(* Logix 5000 project; controller VMPExerciser_1769 1769-L16ER-BB1B rev 30.11; software revision 30.00 *)

TASK MainTask (continuous, watchdog 500 ms) : MainProgram, VMP_Interface

MODULES
   Local : 1769-L16ER-BB1B (PointIO 0, rev 30.11)
      Pump00 : ETHERNET-MODULE (Ethernet 192.168.1.164, rev 1.1, Output RPI 20 ms)
      Pump01 : ETHERNET-MODULE (Ethernet 192.168.1.232, rev 1.1, Output RPI 20 ms)
      Pump02 : ETHERNET-MODULE (Ethernet 192.168.1.167, rev 1.1, Output RPI 20 ms)
      Pump03 : ETHERNET-MODULE (Ethernet 192.168.168.130, rev 1.1, Output RPI 20 ms)
      Discrete_IO : Embedded (PointIO 1, rev 30.11, Output RPI 20 ms)
END_MODULES

TYPE String_16 :   // string type
STRUCT
   LEN : DINT;
   DATA : SINT[16];
END_STRUCT
END_TYPE

TYPE String_20 :   // string type
STRUCT
   LEN : DINT;
   DATA : SINT[20];
END_STRUCT
END_TYPE

TYPE VMP_Cfg :
STRUCT
   ReadyInterlock : BOOL;   // ReadyInterlock
   EthernetRunReady : BOOL;   // EthernetRunReady
   HoldOnFault : BOOL;   // HoldOnFault
   Spare1_3 : BOOL;   // Spare Bit
   Spare1_4 : BOOL;   // Spare Bit
   Spare1_5 : BOOL;   // Spare Bit
   Spare1_6 : BOOL;   // Spare Bit
   Spare1_7 : BOOL;   // Spare Bit
   DecPlaces : SINT;   // DecimalPlaces
   SpareByte1 : SINT;   // Spare data1
   SpareByte2 : SINT;   // Spare data1
END_STRUCT
END_TYPE

TYPE VMP_Device :
STRUCT
   Enabled : BOOL;
   Dispense_Revs : INT;
   Dispense_Rpm : INT;
   Dispense_Vol : REAL;
   Prime_Revs : INT;
   Prime_Rpm : INT;
   Init_DN : BOOL;
   Path : STRING;
   PathFromGSV : SINT[82];
   CFG : VMP_Cfg;
   IN : VMP_IN;
   OUT : VMP_OUT;
   Name : String_16;
END_STRUCT
END_TYPE

TYPE VMP_IN :
STRUCT
   Ready : BOOL;   // Ready to Run
   Running : BOOL;   // Running
   Abort : BOOL;   // Abort State
   Direction : BOOL;   // Direction CCW
   ContinuousRun : BOOL;   // Continuous Run
   MotorRunning : BOOL;   // Motors Running
   AtMaxShot : BOOL;   // AtMaxShot
   CmdAck : BOOL;   // PLC Cmd Ack
   InvalidVolume : BOOL;   // InvaliVolume
   Spare1_9 : BOOL;   // Spare Bit
   Spare1_10 : BOOL;   // Spare Bit
   Spare1_11 : BOOL;   // Spare Bit
   Spare1_12 : BOOL;   // Spare Bit
   Spare1_13 : BOOL;   // Spare Bit
   Spare1_14 : BOOL;   // Spare Bit
   Spare1_15 : BOOL;   // Spare Bit
   Spare1_16 : BOOL;   // Spare Bit
   Spare1_17 : BOOL;   // Spare Bit
   Spare1_18 : BOOL;   // Spare Bit
   Spare1_19 : BOOL;   // Spare Bit
   Spare1_20 : BOOL;   // Spare Bit
   Spare1_21 : BOOL;   // Spare Bit
   Spare1_22 : BOOL;   // Spare Bit
   Spare1_23 : BOOL;   // Spare Bit
   Spare1_24 : BOOL;   // Spare Bit
   Spare1_25 : BOOL;   // Spare Bit
   Spare1_26 : BOOL;   // Spare Bit
   Spare1_27 : BOOL;   // Spare Bit
   Spare1_28 : BOOL;   // Spare Bit
   FaultDispenseMotor : BOOL;   // Disp Motor Fault
   FaultAdjustMotor : BOOL;   // Adj Motor Fault
   FaultAdjustSensor : BOOL;   // Adj Sensor Fault
   CurProgram : DINT;   // Program
   CurRevolutions : DINT;   // Revolutions
   CurVolume : REAL;   // Volume
   CurRpm : DINT;   // RPM
   VolumeDint : DINT;   // Vol as Dint
   Spare_In_DInt2 : DINT;   // Spare data2
   FineAdj : INT;   // FineAdj
   Spare_In_Int1 : INT;   // Spare_In_Int 1
END_STRUCT
END_TYPE

TYPE VMP_OUT :
STRUCT
   OkToRun : BOOL;   // Ok to Run
   Start : BOOL;   // Start
   Abort : BOOL;   // Abort Run
   Direction : BOOL;   // Direction CCW
   ContinuousRun : BOOL;   // Run Continuously
   SetMaxShotSize : BOOL;   // Set Max Volumn
   SetShotSize : BOOL;   // Set Volume
   IgnorePLC : BOOL;   // Ignore PLC Cmds
   IncFineAdj : BOOL;   // IncFineAdj
   DecFineAdj : BOOL;   // DecFineAdj
   ResetRevsCnt : BOOL;   // ResetRevsCnt
   Spare11 : BOOL;   // Spare11
   Spare12 : BOOL;   // Spare12
   Spare13 : BOOL;   // Spare13
   Spare14 : BOOL;   // Spare14
   Spare15 : BOOL;   // Spare15
   Spare16 : BOOL;   // Spare16
   Spare17 : BOOL;   // Spare17
   Spare18 : BOOL;   // Spare18
   Spare19 : BOOL;   // Spare19
   Spare20 : BOOL;   // Spare20
   Spare21 : BOOL;   // Spare21
   Spare22 : BOOL;   // Spare22
   Spare23 : BOOL;   // Spare23
   Spare24 : BOOL;   // Spare24
   Spare25 : BOOL;   // Spare25
   Spare26 : BOOL;   // Spare26
   Spare27 : BOOL;   // Spare27
   Spare28 : BOOL;   // Spare28
   Spare29 : BOOL;   // Spare29
   Spare30 : BOOL;   // Spare30
   Program : DINT;   // Program
   Revolutions : DINT;   // Revolutions
   Volume : REAL;   // Volume
   Rpm : DINT;   // RPM
   Spare_Out_DInt1 : DINT;   // SpareDInt1
   Spare_Out_DInt2 : DINT;   // SpareDInt2
   FineAdjOut : INT;   // FineAdj
   Spare_Out_Int1 : INT;   // Sapre_Out_Int1
END_STRUCT
END_TYPE

TYPE VMP_Prg :
STRUCT
   CalDispenseTime : BOOL;   // CalDispenseTime
   Direction : BOOL;   // Direction CCW
   SetShotSize : BOOL;   // Set Volume
   ContinuousRun : BOOL;   // Run Continuously
   Spare1_4 : BOOL;   // Spare Bit
   Spare1_5 : BOOL;   // Spare Bit
   Spare1_6 : BOOL;   // Spare Bit
   Spare1_7 : BOOL;   // Spare Bit
   Spare1_8 : BOOL;   // Spare Bit
   Spare1_9 : BOOL;   // Spare Bit
   Spare1_10 : BOOL;   // Spare Bit
   Spare1_11 : BOOL;   // Spare Bit
   Spare1_12 : BOOL;   // Spare Bit
   Spare1_13 : BOOL;   // Spare Bit
   Spare1_14 : BOOL;   // Spare Bit
   Spare1_15 : BOOL;   // Spare Bit
   Spare1_16 : BOOL;   // Spare Bit
   Spare1_17 : BOOL;   // Spare Bit
   Spare1_18 : BOOL;   // Spare Bit
   Spare1_19 : BOOL;   // Spare Bit
   Spare1_20 : BOOL;   // Spare Bit
   Spare1_21 : BOOL;   // Spare Bit
   Spare1_22 : BOOL;   // Spare Bit
   Spare1_23 : BOOL;   // Spare Bit
   Spare1_24 : BOOL;   // Spare Bit
   Spare1_25 : BOOL;   // Spare Bit
   Spare1_26 : BOOL;   // Spare Bit
   Spare1_27 : BOOL;   // Spare Bit
   Spare1_28 : BOOL;   // Spare Bit
   Spare1_29 : BOOL;   // Spare Bit
   Spare1_30 : BOOL;   // Spare Bit
   Spare1_31 : BOOL;   // Spare Bit
   Program : DINT;   // Program
   PullBack : DINT;   // PullBack
   InitialRPM : DINT;   // InitialRPM
   RPM : DINT;   // RPM
   FinalRPM : DINT;   // FinalRPM
   FineAdjust : DINT;   // FineAdjust
   Acceleration : DINT;   // Acceleration
   Deceleration : DINT;   // Deceleration
   LoopCycles : DINT;   // LoopCycles
   LinkedProgram : DINT;   // LinkedProgram
   LinkedTimeDelay : DINT;   // LinkedTimeDelay
   MotorCurrent : DINT;   // MotorCurrent
   Revolutions : DINT;   // Revolutions
   AprxDispenseTime : DINT;   // DispenseTime
   Volume : REAL;   // Volume
   ProgramName : String_16;   // ProgramName
END_STRUCT
END_TYPE

ADD_ON_INSTRUCTION ModuleToMSG_Path   (* revision 1.0, vendor Zaxis, Inc *)
VAR_IN_OUT
   Instance_Name : MODULE; {required}
   MsgTag : MESSAGE; {required}
   Pump : VMP_Device; {required}
END_VAR
VAR
   GsvPath : SINT[32]; {access None}
END_VAR

ROUTINE Logic   (* ladder *)
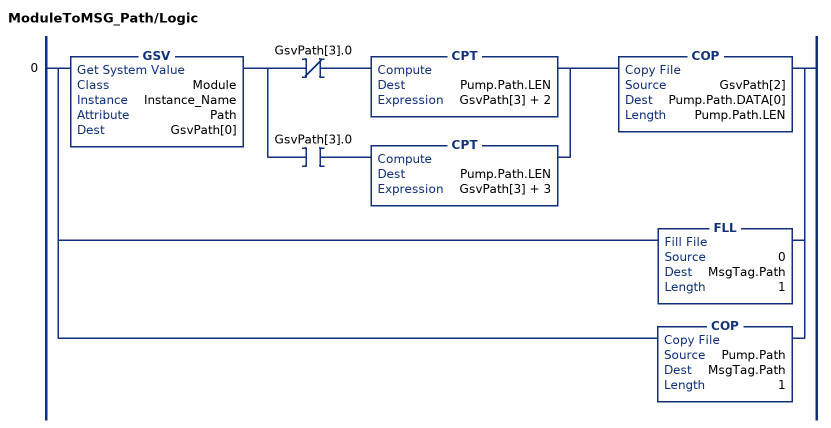
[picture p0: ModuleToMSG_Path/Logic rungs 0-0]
   0: [GSV(Module,Instance_Name,Path,GsvPath[0]) [XIO(GsvPath[3].0) CPT(Pump.Path.LEN,GsvPath[3] + 2) ,XIC(GsvPath[3].0) CPT(Pump.Path.LEN,GsvPath[3] + 3) ] COP(GsvPath[2],Pump.Path.DATA[0],Pump.Path.LEN) ,FLL(0,MsgTag.Path,1) ,COP(Pump.Path,MsgTag.Path,1) ];
END_ROUTINE
END_ADD_ON_INSTRUCTION

ADD_ON_INSTRUCTION VMP_Dispense   (* revision 1.0, vendor Zaxis, Inc *)
VAR_IN_OUT
   Pmp : VMP_Device; {required}
END_VAR
VAR
   DispenseVolDint : DINT; {access None}
END_VAR

ROUTINE Logic   (* ladder *)
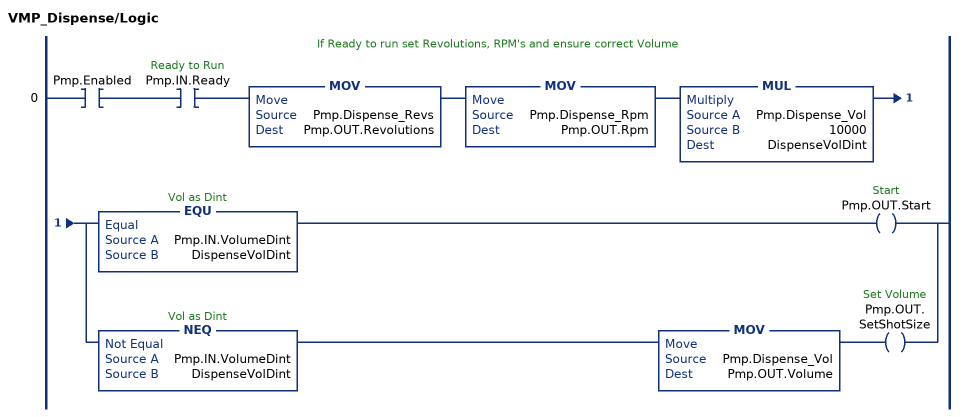
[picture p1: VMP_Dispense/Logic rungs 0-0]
   // If Ready to run set Revolutions, RPM's and ensure correct Volume
   0: XIC(Pmp.Enabled)XIC(Pmp.IN.Ready)MOV(Pmp.Dispense_Revs,Pmp.OUT.Revolutions)MOV(Pmp.Dispense_Rpm,Pmp.OUT.Rpm)MUL(Pmp.Dispense_Vol,10000,DispenseVolDint)[EQU(Pmp.IN.VolumeDint,DispenseVolDint) OTE(Pmp.OUT.Start) ,NEQ(Pmp.IN.VolumeDint,DispenseVolDint) MOV(Pmp.Dispense_Vol,Pmp.OUT.Volume) OTE(Pmp.OUT.SetShotSize) ];
END_ROUTINE
END_ADD_ON_INSTRUCTION

ADD_ON_INSTRUCTION VMP_Initialize   (* revision 1.0 *)
VAR_IN_OUT
   VMP_Module : MODULE; {required}
   Vmp : VMP_Device; {required}
   MsgTag : MESSAGE; {required}
END_VAR
VAR_OUTPUT
   MsgFlags : INT; {access Read Only, visible}
        .2   // EW
        .5   // DN
        .4   // ER
        .6   // ST
        .7   // EN
        .9   // EN_CC
        .8   // TO
END_VAR
VAR
   GsvPath : SINT[32]; {access None}
   PathSet : BOOL; {access None}
END_VAR

ROUTINE Logic   (* ladder *)
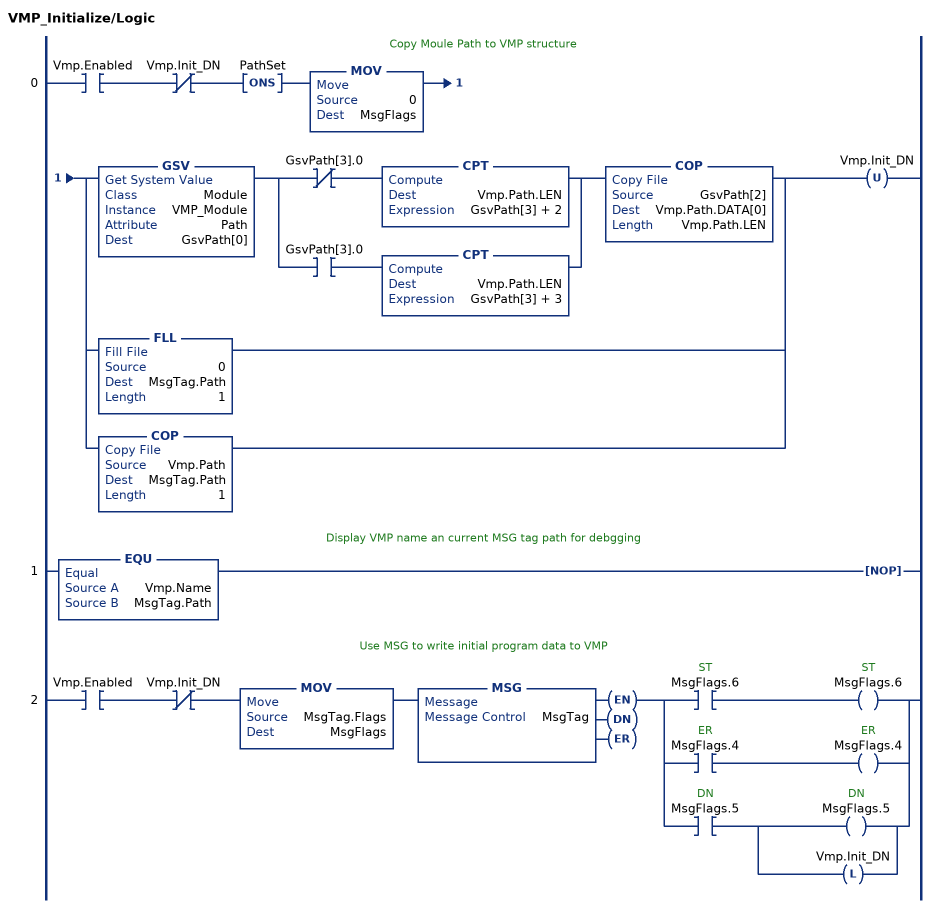
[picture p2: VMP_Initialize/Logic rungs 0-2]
   // Copy Moule Path to VMP structure
   0: XIC(Vmp.Enabled)XIO(Vmp.Init_DN)ONS(PathSet)MOV(0,MsgFlags)[GSV(Module,VMP_Module,Path,GsvPath[0]) [XIO(GsvPath[3].0) CPT(Vmp.Path.LEN,GsvPath[3] + 2) ,XIC(GsvPath[3].0) CPT(Vmp.Path.LEN,GsvPath[3] + 3) ] COP(GsvPath[2],Vmp.Path.DATA[0],Vmp.Path.LEN) ,FLL(0,MsgTag.Path,1) ,COP(Vmp.Path,MsgTag.Path,1) ]OTU(Vmp.Init_DN);
   // Display VMP name an current MSG tag path for debgging
   1: EQU(Vmp.Name,MsgTag.Path)NOP();
   // Use MSG to write initial program data to VMP
   2: XIC(Vmp.Enabled)XIO(Vmp.Init_DN)MOV(MsgTag.Flags,MsgFlags)MSG(MsgTag)[XIC(MsgFlags.6) OTE(MsgFlags.6) ,XIC(MsgFlags.4) OTE(MsgFlags.4) ,XIC(MsgFlags.5) [OTE(MsgFlags.5) ,OTL(Vmp.Init_DN) ] ];
END_ROUTINE
END_ADD_ON_INSTRUCTION

ADD_ON_INSTRUCTION VMP_Initialize1   (* revision 1.0 *)
VAR_IN_OUT
   VMP_Module : MODULE; {required}
   MsgTag : MESSAGE; {required}
   Vmp : VMP_Device; {required}
END_VAR
VAR_OUTPUT
   DN : BOOL; {access Read Only, visible}
   ER : BOOL; {access Read Only, visible}
END_VAR
VAR
   GsvPath : SINT[32]; {access None}
   MSGFlgs : INT; {access None}   // FLAGS
        .2   // EW
        .4   // ER
        .5   // DN
        .6   // ST
        .7   // EN
        .8   // TO
        .9   // EN_CC
END_VAR

ROUTINE Logic   (* ladder *)
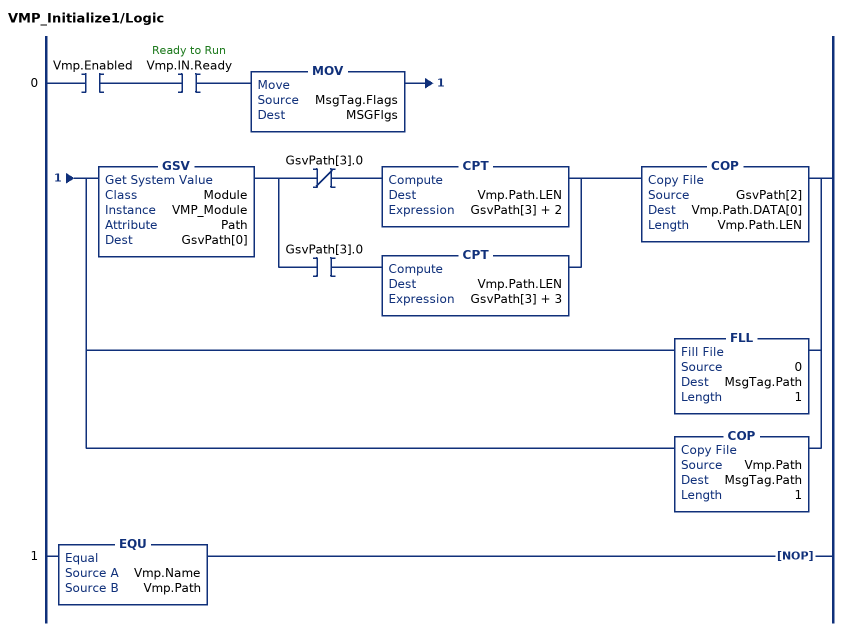
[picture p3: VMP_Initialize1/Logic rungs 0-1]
   0: XIC(Vmp.Enabled)XIC(Vmp.IN.Ready)MOV(MsgTag.Flags,MSGFlgs)[GSV(Module,VMP_Module,Path,GsvPath[0]) [XIO(GsvPath[3].0) CPT(Vmp.Path.LEN,GsvPath[3] + 2) ,XIC(GsvPath[3].0) CPT(Vmp.Path.LEN,GsvPath[3] + 3) ] COP(GsvPath[2],Vmp.Path.DATA[0],Vmp.Path.LEN) ,FLL(0,MsgTag.Path,1) ,COP(Vmp.Path,MsgTag.Path,1) ];
   1: EQU(Vmp.Name,Vmp.Path)NOP();
END_ROUTINE
END_ADD_ON_INSTRUCTION

ADD_ON_INSTRUCTION VMP_Prime   (* revision 1.0, vendor Zaxis, Inc *)
VAR_IN_OUT
   Pmp : VMP_Device; {required}
END_VAR
VAR
   PrimeStarted : BOOL; {access None}
END_VAR

ROUTINE Logic   (* ladder *)
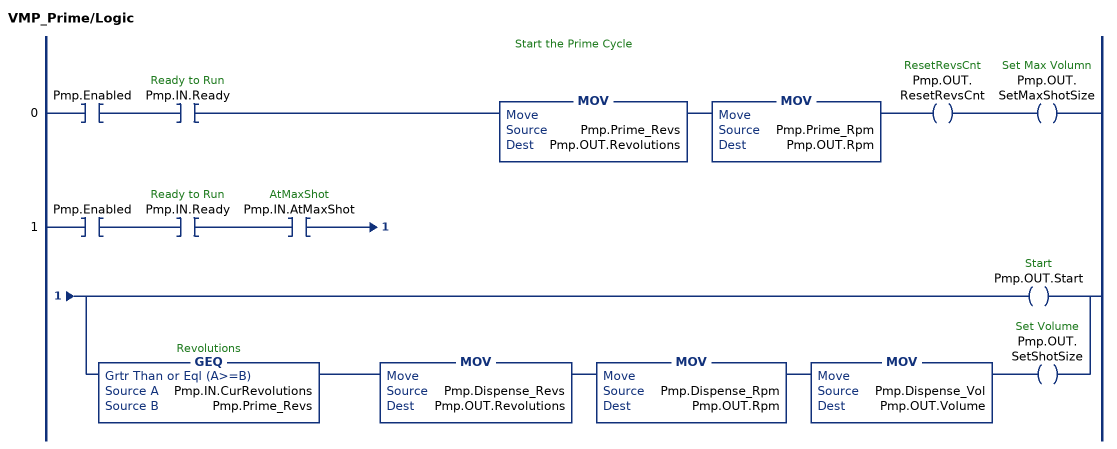
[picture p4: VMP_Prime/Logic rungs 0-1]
   // Start the Prime Cycle
   0: XIC(Pmp.Enabled)XIC(Pmp.IN.Ready)MOV(Pmp.Prime_Revs,Pmp.OUT.Revolutions)MOV(Pmp.Prime_Rpm,Pmp.OUT.Rpm)OTE(Pmp.OUT.ResetRevsCnt)OTE(Pmp.OUT.SetMaxShotSize);
   1: XIC(Pmp.Enabled)XIC(Pmp.IN.Ready)XIC(Pmp.IN.AtMaxShot)[OTE(Pmp.OUT.Start) ,GEQ(Pmp.IN.CurRevolutions,Pmp.Prime_Revs) MOV(Pmp.Dispense_Revs,Pmp.OUT.Revolutions) MOV(Pmp.Dispense_Rpm,Pmp.OUT.Rpm) MOV(Pmp.Dispense_Vol,Pmp.OUT.Volume) OTE(Pmp.OUT.SetShotSize) ];
END_ROUTINE
END_ADD_ON_INSTRUCTION

VAR_GLOBAL   (* controller tags *)
   VMP_Init_Write : MESSAGE;
        MessageParameters(ServiceCode := 16#004d, LocalElement := VMP_Programs[*], ...)
   VMP_Prg_Read : MESSAGE;
        MessageParameters(ServiceCode := 16#0001, DestinationTag := VMP_Programs[3], ...)
   VMP_Prg_Write : MESSAGE;
        MessageParameters(ServiceCode := 16#0002, LocalElement := VMP_Programs[0], ...)
   VMP_Programs : VMP_Prg[4];
END_VAR

PROGRAM MainProgram   (* main routine MainRoutine *)

ROUTINE MainRoutine   (* ladder *)
END_ROUTINE
END_PROGRAM

PROGRAM VMP_Interface   (* main routine PumpMainRoutine *)
VAR
   Buton_Stop : BOOL;
   Button_Go : BOOL;
   Button_Initialize : BOOL;
   Do_Dispense : BOOL := 1;
   Do_Initialize : BOOL := 1;
   Do_Prime : BOOL;
   PmpExr_Run : BOOL;
   PmpExr_Timer : TIMER := (PRE := 12000);
   PmpInt_Cnt : COUNTER := (PRE := 3);
   PmpInt_IncCnt : BOOL := 1;
   PmpPrg_Read : BOOL;
   PmpPrg_Write : BOOL;
   VMP_Dispense : VMP_Dispense;
   VMP_Init : VMP_Initialize := (MsgFlags := 16#0290);
   VMP_Prime : VMP_Prime;
   VMPs : VMP_Device[4];
END_VAR

ROUTINE PumpDispense   (* ladder *)
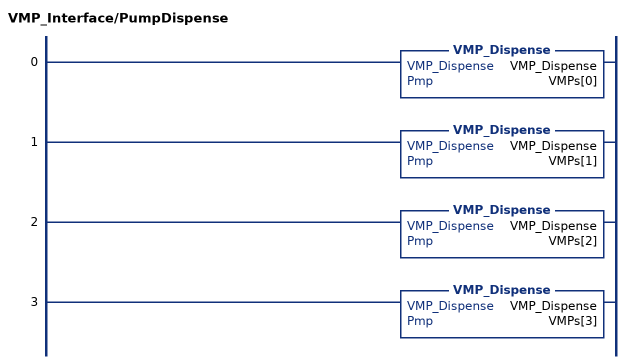
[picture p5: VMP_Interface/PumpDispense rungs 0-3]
   0: VMP_Dispense(VMP_Dispense,VMPs[0]);
   1: VMP_Dispense(VMP_Dispense,VMPs[1]);
   2: VMP_Dispense(VMP_Dispense,VMPs[2]);
   3: VMP_Dispense(VMP_Dispense,VMPs[3]);
END_ROUTINE

ROUTINE PumpExerciser   (* ladder *)
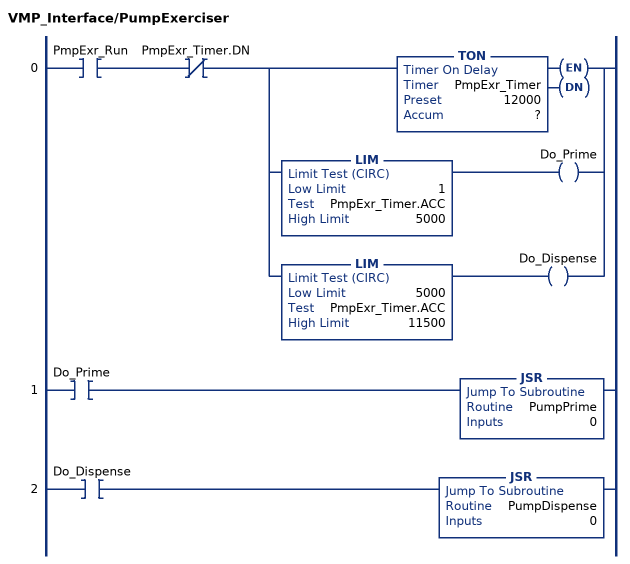
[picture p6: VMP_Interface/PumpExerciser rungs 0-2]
   0: XIC(PmpExr_Run)XIO(PmpExr_Timer.DN)[TON(PmpExr_Timer,?,?) ,LIM(1,PmpExr_Timer.ACC,5000) OTE(Do_Prime) ,LIM(5000,PmpExr_Timer.ACC,11500) OTE(Do_Dispense) ];
   1: XIC(Do_Prime)JSR(PumpPrime,0);
   2: XIC(Do_Dispense)JSR(PumpDispense,0);
END_ROUTINE

ROUTINE PumpMainRoutine   (* ladder *)
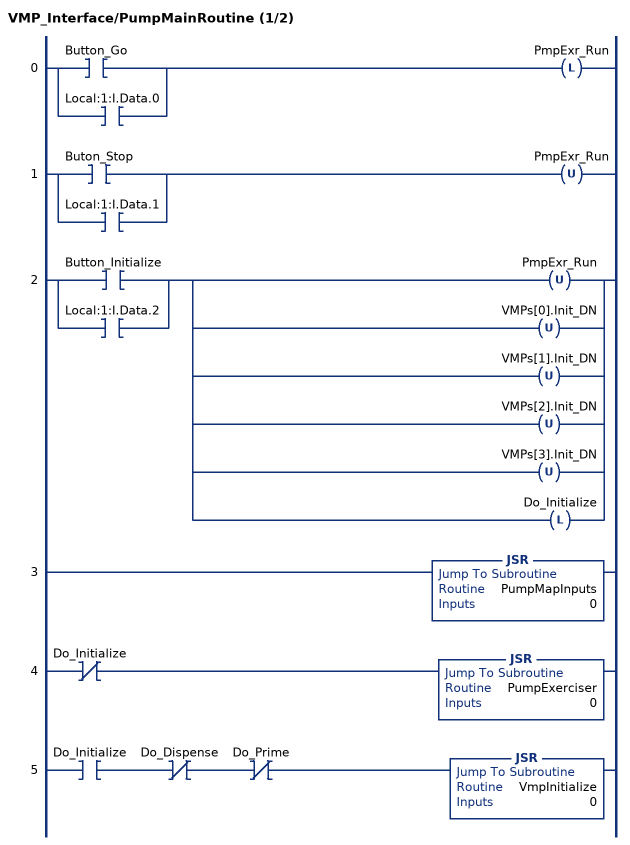
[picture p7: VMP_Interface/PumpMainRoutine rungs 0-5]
   0: [XIC(Button_Go) ,XIC(Local:1:I.Data.0) ]OTL(PmpExr_Run);
   1: [XIC(Buton_Stop) ,XIC(Local:1:I.Data.1) ]OTU(PmpExr_Run);
   2: [XIC(Button_Initialize) ,XIC(Local:1:I.Data.2) ][OTU(PmpExr_Run) ,OTU(VMPs[0].Init_DN) ,OTU(VMPs[1].Init_DN) ,OTU(VMPs[2].Init_DN) ,OTU(VMPs[3].Init_DN) ,OTL(Do_Initialize) ];
   3: JSR(PumpMapInputs,0);
   4: XIO(Do_Initialize)JSR(PumpExerciser,0);
   5: XIC(Do_Initialize)XIO(Do_Dispense)XIO(Do_Prime)JSR(VmpInitialize,0);
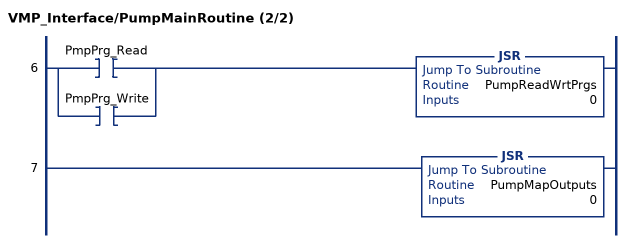
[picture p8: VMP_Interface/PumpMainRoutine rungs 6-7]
   6: [XIC(PmpPrg_Read) ,XIC(PmpPrg_Write) ]JSR(PumpReadWrtPrgs,0);
   7: JSR(PumpMapOutputs,0);
END_ROUTINE

ROUTINE PumpMapInputs   (* ladder *)
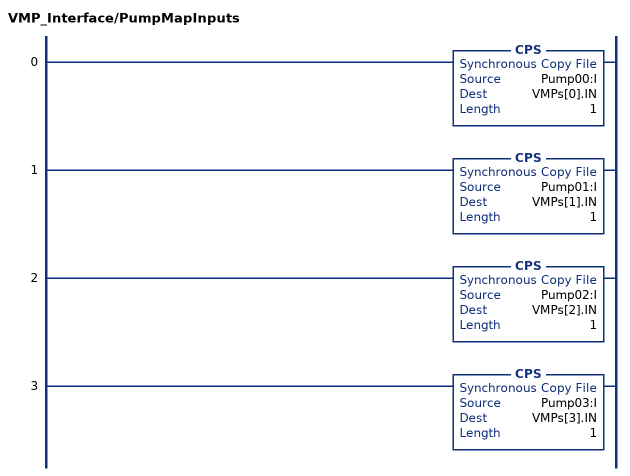
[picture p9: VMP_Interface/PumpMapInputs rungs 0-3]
   0: CPS(Pump00:I,VMPs[0].IN,1);
   1: CPS(Pump01:I,VMPs[1].IN,1);
   2: CPS(Pump02:I,VMPs[2].IN,1);
   3: CPS(Pump03:I,VMPs[3].IN,1);
END_ROUTINE

ROUTINE PumpMapOutputs   (* ladder *)
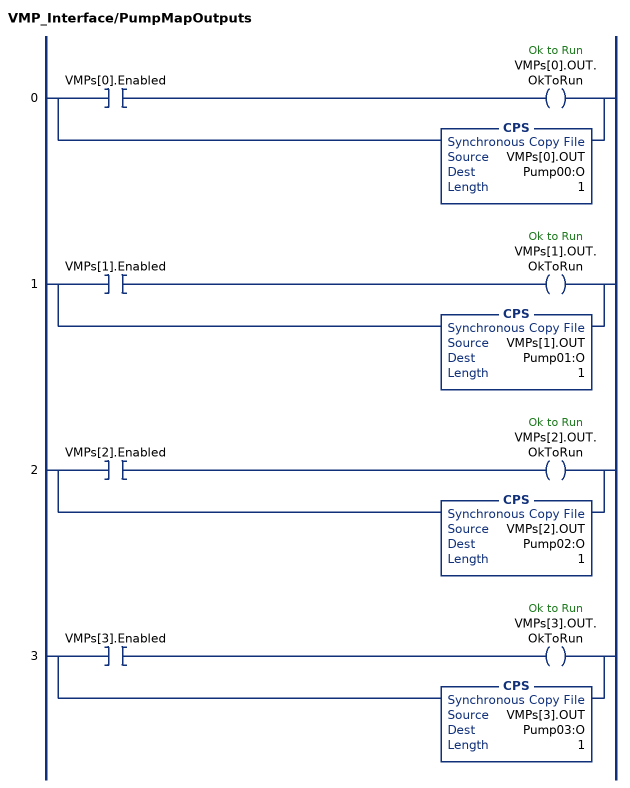
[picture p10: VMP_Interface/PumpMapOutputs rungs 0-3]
   0: [XIC(VMPs[0].Enabled) OTE(VMPs[0].OUT.OkToRun) ,CPS(VMPs[0].OUT,Pump00:O,1) ];
   1: [XIC(VMPs[1].Enabled) OTE(VMPs[1].OUT.OkToRun) ,CPS(VMPs[1].OUT,Pump01:O,1) ];
   2: [XIC(VMPs[2].Enabled) OTE(VMPs[2].OUT.OkToRun) ,CPS(VMPs[2].OUT,Pump02:O,1) ];
   3: [XIC(VMPs[3].Enabled) OTE(VMPs[3].OUT.OkToRun) ,CPS(VMPs[3].OUT,Pump03:O,1) ];
END_ROUTINE

ROUTINE PumpPrime   (* ladder *)
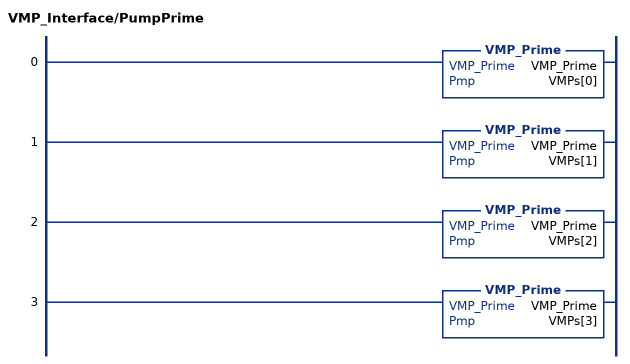
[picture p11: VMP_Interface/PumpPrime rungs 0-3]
   0: VMP_Prime(VMP_Prime,VMPs[0]);
   1: VMP_Prime(VMP_Prime,VMPs[1]);
   2: VMP_Prime(VMP_Prime,VMPs[2]);
   3: VMP_Prime(VMP_Prime,VMPs[3]);
END_ROUTINE

ROUTINE PumpReadWrtPrgs   (* ladder *)
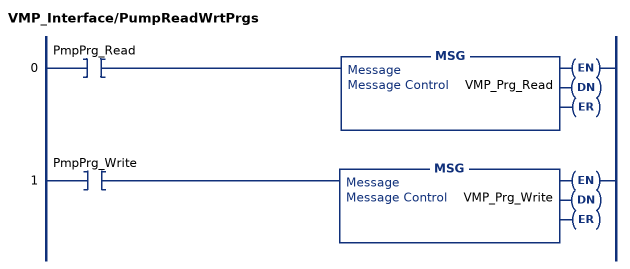
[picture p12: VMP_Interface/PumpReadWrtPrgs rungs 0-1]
   0: XIC(PmpPrg_Read)MSG(VMP_Prg_Read);
   1: XIC(PmpPrg_Write)MSG(VMP_Prg_Write);
END_ROUTINE

ROUTINE VmpInitialize   (* ladder *)
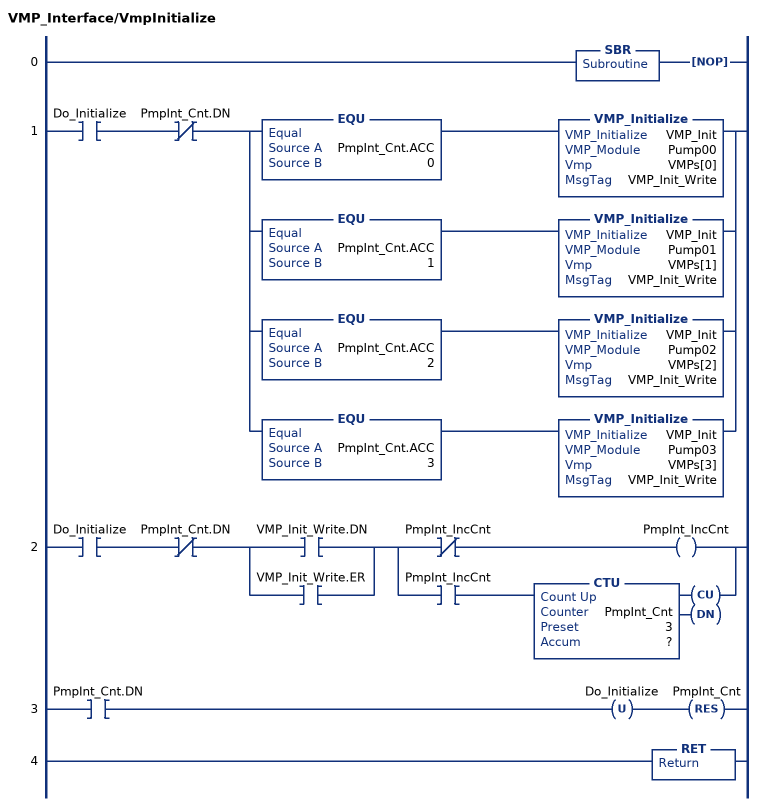
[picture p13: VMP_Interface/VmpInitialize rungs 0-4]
   0: SBR()NOP();
   1: XIC(Do_Initialize)XIO(PmpInt_Cnt.DN)[EQU(PmpInt_Cnt.ACC,0) VMP_Initialize(VMP_Init,Pump00,VMPs[0],VMP_Init_Write) ,EQU(PmpInt_Cnt.ACC,1) VMP_Initialize(VMP_Init,Pump01,VMPs[1],VMP_Init_Write) ,EQU(PmpInt_Cnt.ACC,2) VMP_Initialize(VMP_Init,Pump02,VMPs[2],VMP_Init_Write) ,EQU(PmpInt_Cnt.ACC,3) VMP_Initialize(VMP_Init,Pump03,VMPs[3],VMP_Init_Write) ];
   2: XIC(Do_Initialize)XIO(PmpInt_Cnt.DN)[XIC(VMP_Init_Write.DN) ,XIC(VMP_Init_Write.ER) ][XIO(PmpInt_IncCnt) OTE(PmpInt_IncCnt) ,XIC(PmpInt_IncCnt) CTU(PmpInt_Cnt,?,?) ];
   3: XIC(PmpInt_Cnt.DN)OTU(Do_Initialize)RES(PmpInt_Cnt);
   4: RET();
END_ROUTINE
END_PROGRAM
